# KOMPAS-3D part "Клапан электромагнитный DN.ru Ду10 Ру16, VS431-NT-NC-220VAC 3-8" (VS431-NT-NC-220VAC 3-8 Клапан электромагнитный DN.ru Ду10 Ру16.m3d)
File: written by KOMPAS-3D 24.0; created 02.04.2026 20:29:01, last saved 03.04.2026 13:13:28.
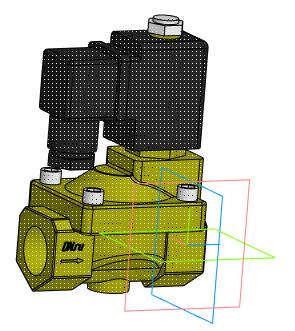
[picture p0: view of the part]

Document properties: Автор: artio; Полное имя файла: C:\Users\artio\OneDrive\Рабочий стол\Клапан электромагнитный DN.ru\VS431\VS431-NT-NC\VS431-NT-NC-220VAC\Ду10\VS431-NT-NC-220VAC 3-8 Клапан электромагнитный DN.ru Ду10 Ру16.m3d

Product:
- Body: Тело 1  | qty 1
    Масса: 1.030062
- Part/product: Клапан электромагнитный DN.ru Ду10 Ру16  | designation VS431-NT-NC-220VAC 3-8
    Масса: 0.62
    Раздел спецификации: Прочие изделия
    Примечание: D130-04667
    additional columns: ef56311e-7521-43dc-8291-0e6108b3d81d; VS400-ET-NC-220VAC 3-8; artio; c; Шероховатость не задана; Да

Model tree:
1. Операция без истории:1

Expressions: VS431-NT-NC-220VAC 3-8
